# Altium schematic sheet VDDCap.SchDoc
size A; SheetNumber: 4; SheetTotal: 6
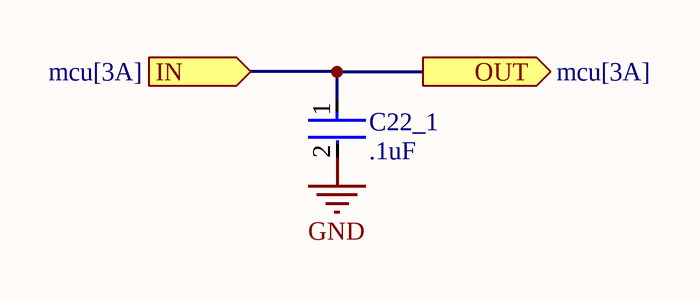
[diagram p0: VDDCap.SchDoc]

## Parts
C22_1  .1uF  [FP-C0603C-CF-MFG]

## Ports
IN (in, see mcu[3A]), OUT (out, see mcu[3A])

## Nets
GND: C22_1.2
IN: C22_1.1 ; port OUT, port IN

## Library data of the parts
C22_1 = CMP-2006-03061-2: CAP CER 0.1UF 50V X7R 0603; Manufacturer: KEMET; Manufacturer Part Number: C0603C104K5RACTU; Tolerance: 0.1; Temperature Coefficient: 30ppm/°C; Material: Ceramic; Automotive Grade: Grade 1; Value: 0.10 μF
